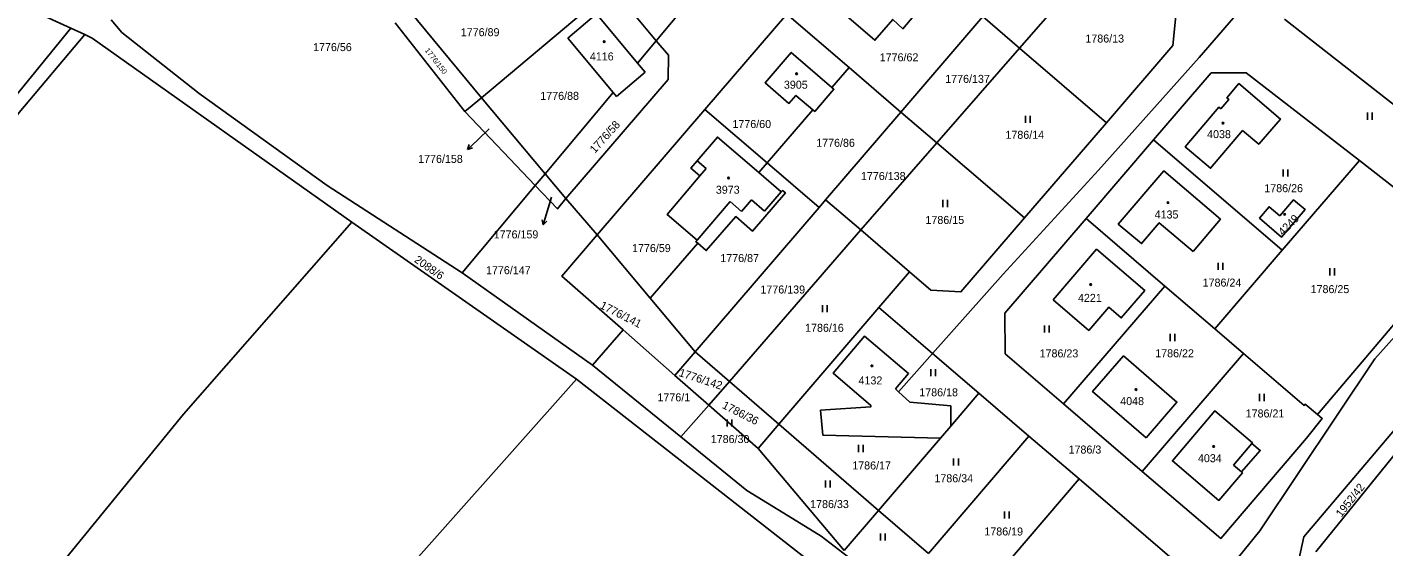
# Model space of a CAD drawing. Extents: x -679220 to -673243, y -1075091 to -1066557.
# Drawn here: x -677014 to -676725.7, y -1072700.8 to -1072590.3 of the extents above; entities that cross this region are included whole.
import ezdxf

# ---------------------------------------------------------------- set-up
doc = ezdxf.new("R2010")
doc.units = 0
for name, color, linetype in [('Hranice parcel', 7, 'Continuous'), ('Parcelní čísla', 7, 'Continuous'), ('Pop  PČ popisy', 7, 'Continuous'), ('Vnitřní kresba', 7, 'Continuous'), ('Značky budov', 7, 'Continuous'), ('Značky kultur', 7, 'Continuous')]:
    doc.layers.add(name, color=color, linetype=linetype)

msp = doc.modelspace()

# ---------------------------------------------------------------- linework, layer by layer
at = {"layer": 'Hranice parcel'}
for p, q in [((-676803.14, -1072594.78), (-676785.53, -1072574.58)), ((-676889.67, -1072582.03), (-676917.41, -1072605.32)), ((-676880.3, -1072593.22), (-676889.67, -1072582.03)), ((-676932.72, -1072586.85), (-676917.41, -1072605.32)), ((-676899.11, -1072592.68), (-676893, -1072587.47)), ((-676893, -1072587.47), (-676884.26, -1072597.96)), ((-676873.78, -1072585.43), (-676880.3, -1072593.22)), ((-676869.99, -1072607.83), (-676852.59, -1072587.54)), ((-676839.32, -1072598.93), (-676852.59, -1072587.54)), ((-677004.68, -1072590.55), (-677017.97, -1072606.91)), ((-677001.71, -1072591.91), (-677004.68, -1072590.55)), ((-676920.96, -1072608.27), (-676935.74, -1072589.39)), ((-676810.93, -1072588.07), (-676828.32, -1072608.38)), ((-676810.93, -1072588.07), (-676803.14, -1072594.78)), ((-676698.62, -1072626.39), (-676746.87, -1072588.6)), ((-676889.48, -1072604.2), (-676899.11, -1072592.68)), ((-676880.3, -1072593.22), (-676884.26, -1072597.96)), ((-676820.73, -1072614.89), (-676803.14, -1072594.78)), ((-676803.14, -1072594.78), (-676784.68, -1072610.67)), ((-676884.26, -1072597.96), (-676882.64, -1072599.9)), ((-676842.99, -1072603.18), (-676839.32, -1072598.93)), ((-676839.32, -1072598.93), (-676828.32, -1072608.38)), ((-676882.64, -1072599.9), (-676888.72, -1072605.1)), ((-676920.96, -1072608.27), (-676917.41, -1072605.32)), ((-676917.41, -1072605.32), (-676903.92, -1072621.47)), ((-676889.48, -1072604.2), (-676903.92, -1072621.47)), ((-676888.72, -1072605.1), (-676889.48, -1072604.2)), ((-676892.88, -1072634.48), (-676869.99, -1072607.83)), ((-676856.77, -1072619.16), (-676869.99, -1072607.83)), ((-676856.77, -1072619.16), (-676847.05, -1072607.89)), ((-676906.02, -1072623.98), (-676920.96, -1072608.27)), ((-676828.32, -1072608.38), (-676844.33, -1072626.99)), ((-676828.32, -1072608.38), (-676820.73, -1072614.89)), ((-676802.09, -1072630.88), (-676784.68, -1072610.67)), ((-676836.87, -1072633.4), (-676820.73, -1072614.89)), ((-676820.73, -1072614.89), (-676802.09, -1072630.88)), ((-676789.01, -1072630.99), (-676774.7, -1072614.28)), ((-676747.31, -1072637.75), (-676774.7, -1072614.28)), ((-676858.55, -1072621.22), (-676856.77, -1072619.16)), ((-676856.77, -1072619.16), (-676845.73, -1072628.62)), ((-676730.94, -1072618.7), (-676747.31, -1072637.75)), ((-676906.02, -1072623.98), (-676903.92, -1072621.47)), ((-676903.92, -1072621.47), (-676899.49, -1072626.77)), ((-676906.02, -1072623.98), (-676921.55, -1072642.56)), ((-676892.88, -1072634.48), (-676899.49, -1072626.77)), ((-676844.33, -1072626.99), (-676845.73, -1072628.62)), ((-676844.33, -1072626.99), (-676836.87, -1072633.4)), ((-676845.73, -1072628.62), (-676872.04, -1072659.32)), ((-676772.28, -1072645.34), (-676789.01, -1072630.99)), ((-676897.25, -1072665.11), (-676944.99, -1072631.78)), ((-676864.78, -1072665.6), (-676836.87, -1072633.4)), ((-676836.87, -1072633.4), (-676826.52, -1072642.3)), ((-676892.88, -1072634.48), (-676881.58, -1072647.94)), ((-676881.58, -1072647.94), (-676871.49, -1072636.24)), ((-676761.66, -1072654.45), (-676747.31, -1072637.75)), ((-676921.55, -1072642.56), (-676893.86, -1072662.18)), ((-676833.03, -1072649.9), (-676826.52, -1072642.3)), ((-676772.28, -1072645.34), (-676793.8, -1072670.38)), ((-676761.66, -1072654.45), (-676772.28, -1072645.34)), ((-676881.58, -1072647.94), (-676872.04, -1072659.32)), ((-676854.27, -1072674.69), (-676833.03, -1072649.9)), ((-676821.6, -1072659.7), (-676833.03, -1072649.9)), ((-676887.37, -1072654.65), (-676893.86, -1072662.18)), ((-676876.33, -1072664.34), (-676887.37, -1072654.65)), ((-676755.59, -1072659.66), (-676761.66, -1072654.45)), ((-676872.04, -1072659.32), (-676876.33, -1072664.34)), ((-676872.04, -1072659.32), (-676864.78, -1072665.6)), ((-676828.83, -1072667.83), (-676821.6, -1072659.7)), ((-676821.6, -1072659.7), (-676811.77, -1072668.12)), ((-676755.59, -1072659.66), (-676777.11, -1072684.72)), ((-676893.86, -1072662.18), (-676875.07, -1072677.42)), ((-676845.4, -1072705.68), (-676897.25, -1072665.11)), ((-676869.15, -1072670.64), (-676876.33, -1072664.34)), ((-676869.15, -1072670.64), (-676864.78, -1072665.6)), ((-676864.78, -1072665.6), (-676854.27, -1072674.69)), ((-676829.49, -1072667.22), (-676828.83, -1072667.83)), ((-676828.83, -1072667.83), (-676826.46, -1072670.05)), ((-676817.76, -1072675.12), (-676811.77, -1072668.12)), ((-676811.77, -1072668.12), (-676801.13, -1072677.24)), ((-676875.07, -1072677.42), (-676869.15, -1072670.64)), ((-676858.67, -1072679.84), (-676869.15, -1072670.64)), ((-676826.46, -1072670.05), (-676817.72, -1072670.82)), ((-676817.72, -1072670.82), (-676817.76, -1072675.12)), ((-676777.11, -1072684.72), (-676793.8, -1072670.38)), ((-676858.67, -1072679.84), (-676854.27, -1072674.69)), ((-676854.27, -1072674.69), (-676833.09, -1072693.01)), ((-676819.92, -1072677.64), (-676844.94, -1072677.02)), ((-676801.13, -1072677.24), (-676822.49, -1072702.18)), ((-676817.76, -1072675.12), (-676819.92, -1072677.64)), ((-676801.13, -1072677.24), (-676790.5, -1072686.34)), ((-676840.42, -1072701.56), (-676858.67, -1072679.84)), ((-676833.09, -1072693.01), (-676819.92, -1072677.64)), ((-676722.71, -1072680.24), (-676740.22, -1072701.84)), ((-676811.92, -1072711.33), (-676790.5, -1072686.34)), ((-676790.5, -1072686.34), (-676769.24, -1072704.56)), ((-676833.09, -1072693.01), (-676840.42, -1072701.56)), ((-676822.49, -1072702.18), (-676833.09, -1072693.01))]:
    msp.add_line(p, q, dxfattribs=at)
for points in [[(-676720.12, -1072543.1), (-676724.33, -1072548.64), (-676735.77, -1072563.02), (-676764.95, -1072596.77), (-676786.33, -1072620.72), (-676806.61, -1072642.84), (-676821.6, -1072659.7)], [(-677004.68, -1072590.55), (-677019.84, -1072583.59), (-677052.27, -1072568.5)], [(-676832.61, -1072573.4), (-676825.17, -1072579.8), (-676825.61, -1072580.32), (-676824.74, -1072581.07), (-676826.56, -1072583.19), (-676823.66, -1072585.67), (-676827.92, -1072590.66), (-676830.07, -1072588.7), (-676833.85, -1072593.13), (-676842.88, -1072585.36), (-676832.61, -1072573.4)], [(-676784.68, -1072610.67), (-676770.55, -1072594.24), (-676769.96, -1072587.9), (-676785.53, -1072574.58)], [(-676921.55, -1072642.56), (-676950.23, -1072623.95), (-676977.42, -1072604.43), (-676993.84, -1072591.45), (-676996.12, -1072588.79)], [(-677186.58, -1072875.08), (-677134.32, -1072781.71), (-677111.61, -1072744.57), (-677046.4, -1072650.91), (-677015.67, -1072608.48), (-677001.71, -1072591.91)], [(-676944.99, -1072631.78), (-677000.12, -1072592.64), (-677001.71, -1072591.91)], [(-676880.3, -1072593.22), (-676877.73, -1072596.3), (-676877.77, -1072601.45), (-676899.49, -1072626.77)], [(-676847.05, -1072607.89), (-676850.63, -1072604.82), (-676852.12, -1072606.52), (-676857.2, -1072602.13), (-676851.63, -1072595.7), (-676842.99, -1072603.18)], [(-676676.04, -1072600.97), (-676689.01, -1072617.2), (-676699.82, -1072629.74), (-676727.69, -1072660.82), (-676752.08, -1072697.33), (-676758.72, -1072705.55), (-676780.51, -1072731.52), (-676784.98, -1072736.24)], [(-676774.7, -1072614.28), (-676762.4, -1072600.05), (-676755, -1072600.05), (-676730.94, -1072618.7)], [(-676760.4, -1072607.7), (-676758.68, -1072605.69), (-676759.08, -1072605.35), (-676756.52, -1072602.33), (-676747.7, -1072609.85), (-676752.32, -1072615.22), (-676755.75, -1072612.31), (-676762.55, -1072620.31), (-676767.93, -1072615.73), (-676760.81, -1072607.36), (-676760.4, -1072607.7)], [(-676842.99, -1072603.18), (-676842.58, -1072603.53), (-676846.64, -1072608.24), (-676847.05, -1072607.89)], [(-676871.49, -1072636.24), (-676871.9, -1072635.88), (-676871.6, -1072635.59), (-676878, -1072630.13), (-676871.03, -1072621.94), (-676872.94, -1072620.3), (-676871.63, -1072618.74), (-676867.33, -1072613.69), (-676858.55, -1072621.22)], [(-676730.94, -1072618.7), (-676718.3, -1072628.48), (-676714.8, -1072638.27), (-676712.57, -1072640.47), (-676739.84, -1072672.64)], [(-676858.55, -1072621.22), (-676853.75, -1072625.34), (-676853.5, -1072625.05), (-676852.86, -1072625.56), (-676859.86, -1072633.66), (-676863.42, -1072630.59), (-676869.67, -1072637.81), (-676871.49, -1072636.24)], [(-676766.22, -1072638.02), (-676773.44, -1072631.91), (-676777.21, -1072636.33), (-676782.16, -1072632.18), (-676772.51, -1072620.89), (-676760.45, -1072631.15), (-676766.22, -1072638.02)], [(-676899.49, -1072626.77), (-676901.31, -1072628.94), (-676906.02, -1072623.98)], [(-676747.85, -1072630.44), (-676744.91, -1072626.99), (-676742.48, -1072629.07), (-676747.47, -1072634.94), (-676752.13, -1072630.92), (-676750.13, -1072628.5), (-676747.85, -1072630.44)], [(-676826.52, -1072642.3), (-676821.97, -1072646.21), (-676815.58, -1072646.61), (-676802.09, -1072630.88)], [(-676793.8, -1072670.38), (-676806.16, -1072659.75), (-676806.25, -1072651.11), (-676789.01, -1072630.99)], [(-677144.26, -1072903.09), (-677089.9, -1072815.17), (-677042.74, -1072748.49), (-676980.72, -1072672.6), (-676944.99, -1072631.78)], [(-676887.37, -1072654.65), (-676900.38, -1072643.22), (-676892.88, -1072634.48)], [(-676795.97, -1072648.25), (-676786.77, -1072637.51), (-676776.53, -1072646.32), (-676781.52, -1072652.13), (-676784.19, -1072649.85), (-676788.44, -1072654.77), (-676795.97, -1072648.25)], [(-676744.49, -1072706.81), (-676742.71, -1072698.63), (-676719.91, -1072671.69), (-676687.51, -1072637.46)], [(-676844.94, -1072677.02), (-676845.41, -1072671.75), (-676834.71, -1072671.01), (-676834.74, -1072670.7), (-676842.76, -1072663.85), (-676836.05, -1072655.98), (-676826.71, -1072663.96), (-676829.49, -1072667.22)], [(-676739.84, -1072672.64), (-676742.46, -1072670.48), (-676742.68, -1072670.73), (-676755.59, -1072659.66)], [(-676776.25, -1072677.59), (-676787.61, -1072667.79), (-676781.04, -1072660.21), (-676769.71, -1072670.01), (-676776.25, -1072677.59)], [(-677097.82, -1072927.19), (-677075, -1072883.37), (-677041.21, -1072831.41), (-677003.98, -1072783.4), (-676995.72, -1072775.93), (-676897.25, -1072665.11)], [(-676739.84, -1072672.64), (-676738.82, -1072673.51), (-676742.18, -1072677.66), (-676760.37, -1072698.98), (-676777.11, -1072684.72)], [(-676753.78, -1072678.79), (-676751.99, -1072680.28), (-676755.96, -1072684.86), (-676755.78, -1072685.01), (-676760.79, -1072690.89), (-676770.67, -1072682.51), (-676761.63, -1072671.85), (-676753.66, -1072678.64), (-676753.78, -1072678.79)], [(-676875.07, -1072677.42), (-676861.09, -1072688.82), (-676852.25, -1072694.17), (-676845.3, -1072698.47), (-676838.82, -1072703.47)]]:
    msp.add_lwpolyline(points, dxfattribs=at)
at = {"layer": 'Pop  PČ popisy'}
for p, q in [((-676915.8, -1072611.95), (-676918.23, -1072614.26)), ((-676918.23, -1072614.26), (-676920.43, -1072616.31)), ((-676920.43, -1072616.31), (-676920.03, -1072615.26)), ((-676920.43, -1072616.31), (-676919.35, -1072615.99)), ((-676902.53, -1072626.44), (-676903.47, -1072629.5)), ((-676904.35, -1072632.37), (-676904.53, -1072631.27)), ((-676903.47, -1072629.5), (-676904.35, -1072632.37)), ((-676904.35, -1072632.37), (-676903.58, -1072631.56))]:
    msp.add_line(p, q, dxfattribs=at)
at = {"layer": 'Vnitřní kresba'}
for p, q in [((-676869.72, -1072620.4), (-676871.63, -1072618.74)), ((-676871.03, -1072621.94), (-676869.72, -1072620.4)), ((-676857.28, -1072629.46), (-676853.75, -1072625.34)), ((-676871.6, -1072635.59), (-676864.61, -1072627.39)), ((-676864.61, -1072627.39), (-676862.17, -1072629.49)), ((-676862.17, -1072629.49), (-676860.04, -1072627.05)), ((-676860.04, -1072627.05), (-676857.28, -1072629.46)), ((-676753.78, -1072678.79), (-676757.68, -1072683.39)), ((-676757.68, -1072683.39), (-676755.96, -1072684.86))]:
    msp.add_line(p, q, dxfattribs=at)
at = {"layer": 'Značky budov'}
for centre in [(-676891.36, -1072593.4), (-676850.51, -1072600.24), (-676759.91, -1072610.73), (-676864.95, -1072622.37), (-676771.59, -1072627.62), (-676746.81, -1072630.11), (-676788.03, -1072645.02), (-676834.5, -1072662.3), (-676778.4, -1072667.34), (-676761.89, -1072679.44)]:
    msp.add_circle(centre, 0.175, dxfattribs=at)
at = {"layer": 'Značky kultur'}
for p, q in [((-676801.9, -1072610.65), (-676801.9, -1072609.15)), ((-676800.9, -1072610.65), (-676800.9, -1072609.15)), ((-676729.21, -1072610), (-676729.21, -1072608.5)), ((-676728.21, -1072610), (-676728.21, -1072608.5)), ((-676747.16, -1072622.06), (-676747.16, -1072620.56)), ((-676746.16, -1072622.06), (-676746.16, -1072620.56)), ((-676819.43, -1072628.56), (-676819.43, -1072627.06)), ((-676818.43, -1072628.56), (-676818.43, -1072627.06)), ((-676760.95, -1072641.88), (-676760.95, -1072640.38)), ((-676759.95, -1072641.88), (-676759.95, -1072640.38)), ((-676737.24, -1072643.07), (-676737.24, -1072641.57)), ((-676736.24, -1072643.07), (-676736.24, -1072641.57)), ((-676845, -1072650.93), (-676845, -1072649.43)), ((-676844, -1072650.93), (-676844, -1072649.43)), ((-676797.82, -1072655.2), (-676797.82, -1072653.7)), ((-676796.82, -1072655.2), (-676796.82, -1072653.7)), ((-676771.14, -1072657.03), (-676771.14, -1072655.53)), ((-676770.14, -1072657.03), (-676770.14, -1072655.53)), ((-676821.96, -1072664.53), (-676821.96, -1072663.03)), ((-676820.96, -1072664.53), (-676820.96, -1072663.03)), ((-676752.19, -1072669.78), (-676752.19, -1072668.28)), ((-676751.19, -1072669.78), (-676751.19, -1072668.28)), ((-676865.26, -1072675.19), (-676865.26, -1072673.69)), ((-676864.26, -1072675.19), (-676864.26, -1072673.69)), ((-676837.36, -1072680.62), (-676837.36, -1072679.12)), ((-676836.36, -1072680.62), (-676836.36, -1072679.12)), ((-676817.13, -1072683.49), (-676817.13, -1072681.99)), ((-676816.13, -1072683.49), (-676816.13, -1072681.99)), ((-676844.33, -1072688.18), (-676844.33, -1072686.68)), ((-676843.33, -1072688.18), (-676843.33, -1072686.68)), ((-676806.34, -1072694.75), (-676806.34, -1072693.25)), ((-676805.34, -1072694.75), (-676805.34, -1072693.25)), ((-676832.65, -1072699.45), (-676832.65, -1072697.95)), ((-676831.65, -1072699.45), (-676831.65, -1072697.95))]:
    msp.add_line(p, q, dxfattribs=at)

# ---------------------------------------------------------------- texts
at = {"layer": 'Parcelní čísla'}
for s, p in [('1776/89', (-676921.83, -1072592.25)), ('1776/56', (-676953.21, -1072595.42)), ('1786/13', (-676789.15, -1072593.6)), ('4116', (-676894.41, -1072597.4)), ('1776/62', (-676832.84, -1072597.59)), ('3905', (-676853.19, -1072603.41)), ('1776/137', (-676818.92, -1072602.17)), ('1776/88', (-676904.94, -1072605.78)), ('1776/60', (-676864.13, -1072611.76)), ('1776/86', (-676846.33, -1072615.76)), ('1786/14', (-676806.13, -1072614.06)), ('4038', (-676763.29, -1072613.92)), ('1776/158', (-676930.89, -1072619.18)), ('1776/138', (-676836.82, -1072622.82)), ('3973', (-676867.65, -1072625.73)), ('1786/26', (-676751.14, -1072625.4)), ('1786/15', (-676823.12, -1072632.15)), ('4135', (-676774.44, -1072630.99)), ('1776/159', (-676914.84, -1072635.22)), ('1776/59', (-676885.45, -1072638.13)), ('1776/87', (-676866.7, -1072640.25)), ('1776/147', (-676916.47, -1072642.83)), ('1776/139', (-676858.18, -1072646.93)), ('1786/24', (-676764.24, -1072645.46)), ('1786/25', (-676741.3, -1072646.85)), ('4221', (-676790.72, -1072648.71)), ('1786/16', (-676848.69, -1072655.07)), ('1786/23', (-676798.87, -1072660.51)), ('1786/22', (-676774.31, -1072660.48)), ('4132', (-676837.34, -1072666.25)), ('1776/1', (-676880.05, -1072669.84)), ('1786/18', (-676824.43, -1072668.78)), ('4048', (-676781.75, -1072670.64)), ('1786/21', (-676755.1, -1072673.27)), ('1786/30', (-676868.73, -1072678.71)), ('1786/3', (-676792.72, -1072680.94)), ('1786/17', (-676838.67, -1072684.32)), ('4034', (-676765.24, -1072682.78)), ('1786/34', (-676821.22, -1072687.04)), ('1786/33', (-676847.62, -1072692.53)), ('1786/19', (-676810.61, -1072698.35))]:
    msp.add_text(s, height=1.7, dxfattribs=at).set_placement(p)
for s, height, rotation, p in [('1776/150', 1.139, 308, (-676929.55, -1072595.28)), ('1776/58', 1.7, 48, (-676893.35, -1072617.26)), ('4249', 1.7, 45, (-676747.19, -1072634.75)), ('2088/6', 1.7, 325, (-676931.86, -1072640.11)), ('1776/141', 1.7, 333, (-676892.42, -1072649.98)), ('1776/142', 1.7, 342, (-676875.63, -1072664.44)), ('1786/36', 1.7, 333, (-676866.45, -1072671.21)), ('1952/42', 1.7, 52, (-676734.76, -1072694.6))]:
    msp.add_text(s, height=height, rotation=rotation, dxfattribs=at).set_placement(p)

doc.saveas('drawing.dxf')
